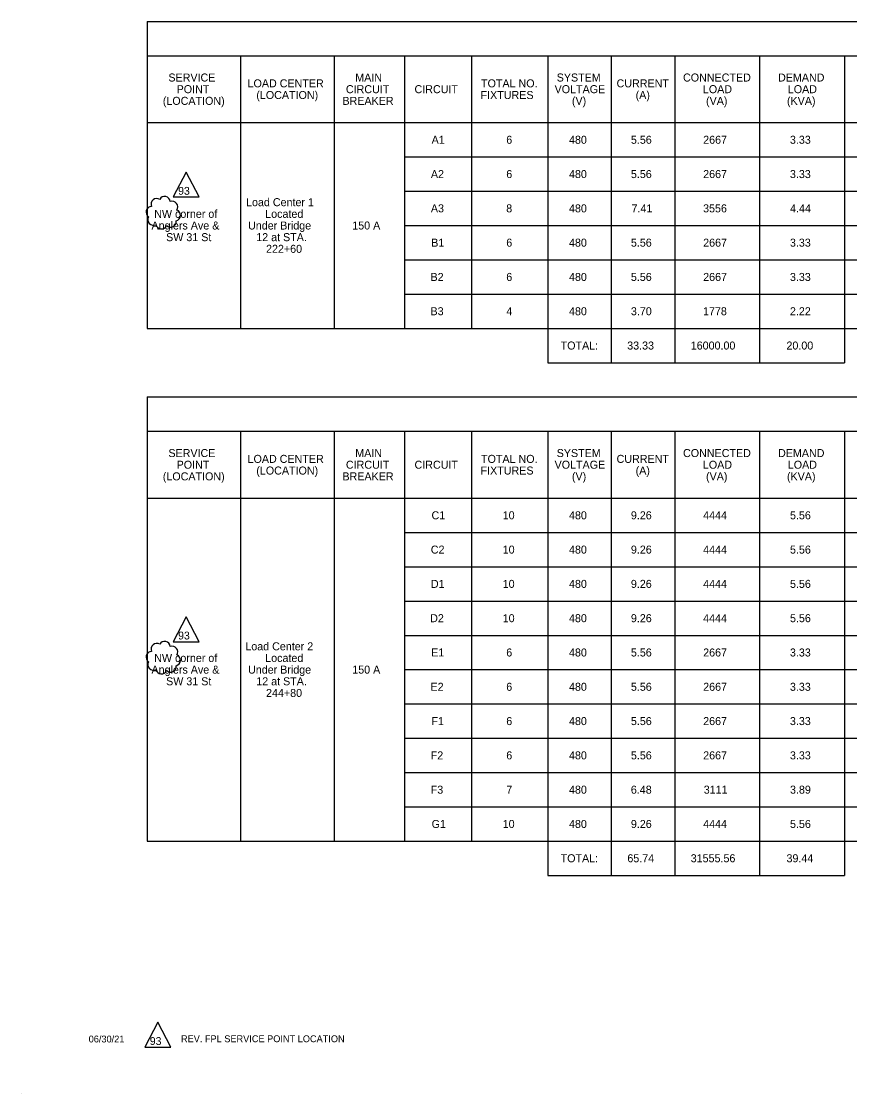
# Model space of a CAD drawing. Extents: x -0.6 to 15.3, y -0.9 to 8.5.
# Drawn here: x -0.55 to 6.69, y -0.9 to 8.48 of the extents above; entities that cross this region are included whole.
import ezdxf

# ---------------------------------------------------------------- set-up
doc = ezdxf.new("R2010")
doc.units = 0
for name, color, linetype in [('AdhocPoint_dp', 7, 'Continuous'), ('Cloud_dp', 7, 'Continuous'), ('SumBoxBorder_dp', 7, 'Continuous'), ('SumBoxLines_dp', 7, 'Continuous'), ('TextLabel', 7, 'Continuous')]:
    doc.layers.add(name, color=color, linetype=linetype)

msp = doc.modelspace()

# ---------------------------------------------------------------- linework, layer by layer
at = {"layer": 'AdhocPoint_dp'}
msp.add_line((-0.55, -0.9), (-0.55, -0.9), dxfattribs=at)
at = {"layer": 'Cloud_dp'}
for points in [[(0.8899, 7.16), (0.7772, 6.9428), (1.0027, 6.9428)], [(0.8899, 3.2701), (0.7772, 3.0529), (1.0027, 3.0529)]]:
    msp.add_lwpolyline(points, close=True, dxfattribs=at)
for centre, start, end in [((0.7013, 6.8977), 5.26643, 150.26643), ((0.5888, 6.8106), 91.02771, 236.02771), ((0.633, 6.8799), 58.89856, 203.89856), ((0.7678, 6.8561), 325.66858, 110.66858), ((0.604, 6.7452), 150.2055, 295.2055), ((0.7915, 6.782), 284.78291, 69.78291), ((0.673, 6.7123), 193.64123, 338.64123), ((0.7552, 6.7278), 222.692, 7.692), ((0.633, 2.988), 58.89856, 203.89856), ((0.7013, 3.0057), 5.26643, 150.26643), ((0.7678, 2.9641), 325.66858, 110.66858), ((0.5888, 2.9187), 91.02771, 236.02771), ((0.7915, 2.8901), 284.78291, 69.78291), ((0.604, 2.8533), 150.2055, 295.2055), ((0.7552, 2.8358), 222.692, 7.692), ((0.673, 2.8203), 193.64123, 338.64123)]:
    msp.add_arc(centre, 0.0493, start, end, dxfattribs=at)
at = {"layer": 'SumBoxBorder_dp'}
for p, q in [((0.5487, 8.4783), (14.8513, 8.4783)), ((0.5487, 8.4783), (0.5487, 5.7933)), ((0.5487, 8.1783), (14.8513, 8.1783)), ((0.5487, 8.1783), (14.8513, 8.1783)), ((0.5487, 5.7933), (14.8513, 5.7933)), ((0.5487, 5.7933), (14.8513, 5.7933)), ((4.0513, 5.7933), (4.0513, 5.4933)), ((6.6462, 5.7933), (6.6462, 5.4933)), ((6.6462, 5.7933), (6.6462, 5.4933)), ((4.0513, 5.4933), (6.6462, 5.4933)), ((4.0513, 5.4933), (6.6462, 5.4933)), ((0.5487, 5.1933), (14.8513, 5.1933)), ((0.5487, 5.1933), (0.5487, 1.3083)), ((0.5487, 4.8933), (14.8513, 4.8933)), ((0.5487, 4.8933), (14.8513, 4.8933)), ((0.5487, 1.3083), (14.8513, 1.3083)), ((0.5487, 1.3083), (14.8513, 1.3083)), ((4.0513, 1.3083), (4.0513, 1.0083)), ((6.6462, 1.3083), (6.6462, 1.0083)), ((6.6462, 1.3083), (6.6462, 1.0083)), ((4.0513, 1.0083), (6.6462, 1.0083))]:
    msp.add_line(p, q, dxfattribs=at)
at = {"layer": 'SumBoxLines_dp'}
for p, q in [((1.3662, 8.1783), (1.3662, 5.7933)), ((1.3662, 8.1783), (1.3662, 5.7933)), ((2.1837, 8.1783), (2.1837, 5.7933)), ((2.1837, 8.1783), (2.1837, 5.7933)), ((2.7987, 8.1783), (2.7987, 5.7933)), ((2.7987, 8.1783), (2.7987, 5.7933)), ((3.3837, 8.1783), (3.3837, 5.7933)), ((3.3837, 8.1783), (3.3837, 5.7933)), ((4.0513, 8.1783), (4.0513, 5.7933)), ((4.0513, 8.1783), (4.0513, 5.7933)), ((4.6063, 8.1783), (4.6063, 5.4933)), ((4.6063, 8.1783), (4.6063, 5.4933)), ((5.1612, 8.1783), (5.1612, 5.4933)), ((5.1612, 8.1783), (5.1612, 5.4933)), ((5.9037, 8.1783), (5.9037, 5.4933)), ((5.9037, 8.1783), (5.9037, 5.4933)), ((6.6462, 8.1783), (6.6462, 5.7933)), ((6.6462, 8.1783), (6.6462, 5.7933)), ((0.5487, 7.5933), (14.8513, 7.5933)), ((0.5487, 7.5933), (14.8513, 7.5933)), ((2.7987, 7.2933), (14.8513, 7.2933)), ((2.7987, 7.2933), (14.8513, 7.2933)), ((2.7987, 6.9933), (14.8513, 6.9933)), ((2.7987, 6.9933), (14.8513, 6.9933)), ((2.7987, 6.6933), (14.8513, 6.6933)), ((2.7987, 6.6933), (14.8513, 6.6933)), ((2.7987, 6.3933), (14.8513, 6.3933)), ((2.7987, 6.3933), (14.8513, 6.3933)), ((2.7987, 6.0933), (14.8513, 6.0933)), ((2.7987, 6.0933), (14.8513, 6.0933)), ((1.3662, 4.8933), (1.3662, 1.3083)), ((1.3662, 4.8933), (1.3662, 1.3083)), ((2.1837, 4.8933), (2.1837, 1.3083)), ((2.1837, 4.8933), (2.1837, 1.3083)), ((2.7987, 4.8933), (2.7987, 1.3083)), ((2.7987, 4.8933), (2.7987, 1.3083)), ((3.3837, 4.8933), (3.3837, 1.3083)), ((3.3837, 4.8933), (3.3837, 1.3083)), ((4.0513, 4.8933), (4.0513, 1.3083)), ((4.0513, 4.8933), (4.0513, 1.3083)), ((4.6063, 4.8933), (4.6063, 1.0083)), ((4.6063, 4.8933), (4.6063, 1.0083)), ((5.1612, 4.8933), (5.1612, 1.0083)), ((5.1612, 4.8933), (5.1612, 1.0083)), ((5.9037, 4.8933), (5.9037, 1.0083)), ((5.9037, 4.8933), (5.9037, 1.0083)), ((6.6462, 4.8933), (6.6462, 1.3083)), ((6.6462, 4.8933), (6.6462, 1.3083)), ((0.5487, 4.3083), (14.8513, 4.3083)), ((0.5487, 4.3083), (14.8513, 4.3083)), ((2.7987, 4.0083), (14.8513, 4.0083)), ((2.7987, 4.0083), (14.8513, 4.0083)), ((2.7987, 3.7083), (14.8513, 3.7083)), ((2.7987, 3.7083), (14.8513, 3.7083)), ((2.7987, 3.4083), (14.8513, 3.4083)), ((2.7987, 3.4083), (14.8513, 3.4083)), ((2.7987, 3.1083), (14.8513, 3.1083)), ((2.7987, 3.1083), (14.8513, 3.1083)), ((2.7987, 2.8083), (14.8513, 2.8083)), ((2.7987, 2.8083), (14.8513, 2.8083)), ((2.7987, 2.5083), (14.8513, 2.5083)), ((2.7987, 2.5083), (14.8513, 2.5083)), ((2.7987, 2.2083), (14.8513, 2.2083)), ((2.7987, 2.2083), (14.8513, 2.2083)), ((2.7987, 1.9083), (14.8513, 1.9083)), ((2.7987, 1.9083), (14.8513, 1.9083)), ((2.7987, 1.6083), (14.8513, 1.6083)), ((2.7987, 1.6083), (14.8513, 1.6083))]:
    msp.add_line(p, q, dxfattribs=at)
at = {"layer": 'TextLabel'}
msp.add_lwpolyline([(0.6421, -0.2768), (0.5294, -0.4939), (0.7549, -0.4939)], close=True, dxfattribs=at)

# ---------------------------------------------------------------- texts
at = {"layer": 'Cloud_dp'}
for p in [(0.82, 6.9622), (0.82, 3.0722)]:
    msp.add_text('93', height=0.06846, rotation=0, dxfattribs=at).set_placement(p)
at = {"layer": 'TextLabel'}
for s, p in [('SERVICE', (0.7349, 7.9528)), ('LOAD CENTER', (1.427, 7.9018)), ('MAIN', (2.3686, 7.9528)), ('TOTAL NO.', (3.4682, 7.9018)), ('SYSTEM', (4.1296, 7.9528)), ('CURRENT', (4.6533, 7.9018)), ('CONNECTED', (5.2343, 7.9528)), ('DEMAND', (6.0649, 7.9528)), ('POINT', (0.8068, 7.8508)), ('CIRCUIT', (2.2867, 7.8508)), ('CIRCUIT', (2.8867, 7.8508)), ('VOLTAGE', (4.1114, 7.8508)), ('LOAD', (5.4079, 7.8508)), ('LOAD', (6.1504, 7.8508)), ('(LOCATION)', (0.686, 7.7488)), ('(LOCATION)', (1.5035, 7.7998)), ('BREAKER', (2.2564, 7.7488)), ('FIXTURES', (3.4643, 7.7998)), ('(V)', (4.2629, 7.7488)), ('(A)', (4.8199, 7.7998)), ('(VA)', (5.4354, 7.7488)), ('(KVA)', (6.1431, 7.7488)), ('A1', (3.0361, 7.4083)), ('6', (3.6889, 7.4083)), ('480', (4.2374, 7.4083)), ('5.56', (4.7785, 7.4083)), ('2667', (5.4105, 7.4083)), ('3.33', (6.169, 7.4083)), ('A2', (3.0298, 7.1083)), ('6', (3.6889, 7.1083)), ('480', (4.2374, 7.1083)), ('5.56', (4.7785, 7.1083)), ('2667', (5.4105, 7.1083)), ('3.33', (6.169, 7.1083)), ('Load Center 1', (1.4138, 6.8623)), ('A3', (3.0298, 6.8083)), ('8', (3.6884, 6.8083)), ('480', (4.2374, 6.8083)), ('7.41', (4.7841, 6.8083)), ('3556', (5.4096, 6.8083)), ('4.44', (6.1704, 6.8083)), ('NW corner of', (0.6107, 6.7603)), ('Located', (1.5812, 6.7603)), ('Anglers Ave &', (0.5871, 6.6583)), ('Under Bridge', (1.4313, 6.6583)), ('150 A', (2.3424, 6.6583)), ('SW 31 St', (0.7148, 6.5563)), ('12 at STA.', (1.503, 6.5563)), ('B1', (3.0328, 6.5083)), ('6', (3.6889, 6.5083)), ('480', (4.2374, 6.5083)), ('5.56', (4.7785, 6.5083)), ('2667', (5.4105, 6.5083)), ('3.33', (6.169, 6.5083)), ('222+60', (1.5884, 6.4543)), ('B2', (3.0265, 6.2083)), ('6', (3.6889, 6.2083)), ('480', (4.2374, 6.2083)), ('5.56', (4.7785, 6.2083)), ('2667', (5.4105, 6.2083)), ('3.33', (6.169, 6.2083)), ('B3', (3.0265, 5.9083)), ('4', (3.6895, 5.9083)), ('480', (4.2374, 5.9083)), ('3.70', (4.7786, 5.9083)), ('1778', (5.4091, 5.9083)), ('2.22', (6.169, 5.9083)), ('TOTAL:', (4.1642, 5.6083)), ('33.33', (4.7463, 5.6083)), ('16000.00', (5.3017, 5.6083)), ('20.00', (6.1385, 5.6083)), ('SERVICE', (0.7349, 4.6678)), ('MAIN', (2.3686, 4.6678)), ('SYSTEM', (4.1296, 4.6678)), ('CONNECTED', (5.2343, 4.6678)), ('DEMAND', (6.0649, 4.6678)), ('POINT', (0.8068, 4.5658)), ('LOAD CENTER', (1.427, 4.6168)), ('CIRCUIT', (2.2867, 4.5658)), ('CIRCUIT', (2.8867, 4.5658)), ('TOTAL NO.', (3.4682, 4.6168)), ('VOLTAGE', (4.1114, 4.5658)), ('CURRENT', (4.6533, 4.6168)), ('LOAD', (5.4079, 4.5658)), ('LOAD', (6.1504, 4.5658)), ('(LOCATION)', (0.686, 4.4638)), ('(LOCATION)', (1.5035, 4.5148)), ('BREAKER', (2.2564, 4.4638)), ('FIXTURES', (3.4643, 4.5148)), ('(V)', (4.2629, 4.4638)), ('(A)', (4.8199, 4.5148)), ('(VA)', (5.4354, 4.4638)), ('(KVA)', (6.1431, 4.4638)), ('C1', (3.0354, 4.1233)), ('10', (3.6576, 4.1233)), ('480', (4.2374, 4.1233)), ('9.26', (4.7785, 4.1233)), ('4444', (5.4103, 4.1233)), ('5.56', (6.1697, 4.1233)), ('C2', (3.0291, 3.8233)), ('10', (3.6576, 3.8233)), ('480', (4.2374, 3.8233)), ('9.26', (4.7785, 3.8233)), ('4444', (5.4103, 3.8233)), ('5.56', (6.1697, 3.8233)), ('D1', (3.0298, 3.5233)), ('10', (3.6576, 3.5233)), ('480', (4.2374, 3.5233)), ('9.26', (4.7785, 3.5233)), ('4444', (5.4103, 3.5233)), ('5.56', (6.1697, 3.5233)), ('D2', (3.0235, 3.2233)), ('10', (3.6576, 3.2233)), ('480', (4.2374, 3.2233)), ('9.26', (4.7785, 3.2233)), ('4444', (5.4103, 3.2233)), ('5.56', (6.1697, 3.2233)), ('Load Center 2', (1.4075, 2.9773)), ('NW corner of', (0.6107, 2.8753)), ('Located', (1.5812, 2.8753)), ('E1', (3.0325, 2.9233)), ('6', (3.6889, 2.9233)), ('480', (4.2374, 2.9233)), ('5.56', (4.7785, 2.9233)), ('2667', (5.4105, 2.9233)), ('3.33', (6.169, 2.9233)), ('Anglers Ave &', (0.5871, 2.7733)), ('Under Bridge', (1.4313, 2.7733)), ('150 A', (2.3424, 2.7733)), ('SW 31 St', (0.7148, 2.6713)), ('12 at STA.', (1.503, 2.6713)), ('244+80', (1.5884, 2.5693)), ('E2', (3.0262, 2.6233)), ('6', (3.6889, 2.6233)), ('480', (4.2374, 2.6233)), ('5.56', (4.7785, 2.6233)), ('2667', (5.4105, 2.6233)), ('3.33', (6.169, 2.6233)), ('F1', (3.0346, 2.3233)), ('6', (3.6889, 2.3233)), ('480', (4.2374, 2.3233)), ('5.56', (4.7785, 2.3233)), ('2667', (5.4105, 2.3233)), ('3.33', (6.169, 2.3233)), ('F2', (3.0283, 2.0233)), ('6', (3.6889, 2.0233)), ('480', (4.2374, 2.0233)), ('5.56', (4.7785, 2.0233)), ('2667', (5.4105, 2.0233)), ('3.33', (6.169, 2.0233)), ('F3', (3.0283, 1.7233)), ('7', (3.6897, 1.7233)), ('480', (4.2374, 1.7233)), ('6.48', (4.778, 1.7233)), ('3111', (5.4152, 1.7233)), ('3.89', (6.1697, 1.7233)), ('G1', (3.0362, 1.4233)), ('10', (3.6576, 1.4233)), ('480', (4.2374, 1.4233)), ('9.26', (4.7785, 1.4233)), ('4444', (5.4103, 1.4233)), ('5.56', (6.1697, 1.4233)), ('TOTAL:', (4.1642, 1.1233)), ('65.74', (4.7477, 1.1233)), ('31555.56', (5.3015, 1.1233)), ('39.44', (6.139, 1.1233))]:
    msp.add_text(s, height=0.07, dxfattribs=at).set_placement(p)
for s, height, rotation, p in [('06/30/21', 0.06, 360, (0.0377, -0.453)), ('93', 0.06846, 0, (0.5722, -0.4746)), ('REV. FPL SERVICE POINT LOCATION', 0.06, 360, (0.8445, -0.4508))]:
    msp.add_text(s, height=height, rotation=rotation, dxfattribs=at).set_placement(p)

doc.saveas('drawing.dxf')
